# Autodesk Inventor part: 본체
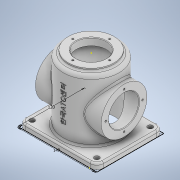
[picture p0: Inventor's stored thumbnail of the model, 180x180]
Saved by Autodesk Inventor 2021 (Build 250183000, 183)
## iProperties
Created: 2021-02
Part Number: 본체
Material: 알루미늄 6061
Document SubType Name: Modeling
Designer: mdu2-97
Density: 2.7 g/cm^3
Appearance: 기본값
Mass: 1251.31 g
Surface Area: 1080.97 cm^2
Volume: 463.448 cm^3
Author: mdu2-97
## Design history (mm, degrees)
sketch "스케치1"
  geometry: L1 (-70, -60)-(70, -60); L2 (70, -60)-(70, 60); L3 (70, 60)-(-70, 60); L4 (-70, 60)-(-70, -60); L5 (-70, -60)-(70, 60); L6 (70, -60)-(-70, 60); 1 further point
  constraints: 12 end point, 2 midpoint, 2 parallel, 1 horizontal, 1 perpendicular
  dimensions: "d0" = 140 distance of L3.end L2.end; "d1" = 120 distance of L2.end L1.end
extrude "돌출1" new body sketch "스케치1" distance "d2" = 10; taper "d3" = 0 deg
sketch "스케치2"
  geometry: 1 further point
sketch "스케치3"
  geometry: C1 r 50 at (0, 0); 1 further point
  constraints: 1 centre point, 1 coincident
  dimensions: "d4" = 100 diameter of C1
extrude "돌출2" join sketch "스케치3" distance "d5" = 110; taper "d6" = 0 deg
sketch "스케치6"
  geometry: 1 further point
sketch "스케치7"
  geometry: C1 r 27 at (0, 0); 1 further point
  constraints: 1 centre point, 1 coincident
  dimensions: "d12" = 54 diameter of C1
extrude "돌출4" cut sketch "스케치7" distance "d13" = 8; taper "d14" = 0 deg
sketch "스케치8"
  geometry: C1 r 42 at (0, 0); 1 further point
  constraints: 1 centre point, 1 coincident
  dimensions: "d15" = 84 diameter of C1
extrude "돌출5" cut sketch "스케치8" extent not by distance; stored distance "d16" = 0; taper "d17" = 0 deg
sketch "스케치9"
  geometry: C1 r 41 at (0, 0); 1 further point
  constraints: 1 centre point, 1 coincident
  dimensions: "d18" = 82 diameter of C1
extrude "돌출6" join sketch "스케치9" distance "d19" = 5; taper "d20" = 0 deg
sketch "스케치10"
  geometry: C1 r 27 at (0, 0) reference; 1 further point
extrude "돌출7" cut sketch "스케치10" extent not by distance; stored distance "d21" = 5; taper "d22" = 0 deg
fillet "모깎기1" dims "d23" = 6
fillet "모깎기2" dims "d24" = 3
node "작업 평면1"
sketch "스케치11"
  geometry: L1 (10, 60)-(10, -60) reference; L2 (125, -41)-(125, 41) reference; L3 (0, 60)-(0, -60) reference; L4 (10, 50)-(10, -50) reference; L5 (114, -50)-(114, 50) reference; L6 (114, 0)-(10, 0); C1 r 41 at (60, 0); 1 further point
  constraints: 2 end point, 2 midpoint, 1 centre point, 1 point on line
  dimensions: "d26" = 82 diameter of C1; "d27" = 60 distance from line of C1.centre L3
extrude "돌출8" join sketch "스케치11" stored distance "d28" = 5; taper "d29" = 0 deg
sketch "스케치12"
  geometry: C1 r 27 at (0, 0); C2 r 41 at (0, 0) reference; 1 further point
  constraints: 1 centre point, 1 coincident
  dimensions: "d30" = 54 diameter of C1
extrude "돌출9" cut sketch "스케치12" stored distance "d31" = 5; taper "d32" = 0 deg
fillet "모깎기3" dims "d33" = 3
sketch "스케치13"
  geometry: 1 further point
fillet "모깎기4" dims "d34" = 12
sketch "스케치14"
  geometry: C1 r 4.5 at (-58, -48); A1 r 12 centre (-58, -48) between (-70, -48) and (-58, -60) reference; A2 r 12 centre (-58, 48) between (-58, 60) and (-70, 48) reference; A3 r 12 centre (58, 48) between (70, 48) and (58, 60) reference; A4 r 12 centre (58, -48) between (58, -60) and (70, -48) reference; 1 further point
  constraints: 1 centre point, 1 coincident
  dimensions: "d35" = 9 diameter of C1
extrude "돌출10" cut sketch "스케치14" extent not by distance; stored distance "d36" = 0; taper "d37" = 0 deg
sketch "스케치15" dims "d38" = 66
  geometry: 3 further points
  constraints: 1 vertical alignment, 2 other
hole "구멍1" sketch "스케치15" at (0, 33) diameter "d39" = 3.242; stored, may be unused: countersink angle "d43" = 90 deg, drill point angle "d45" = 118 deg; dims "d40" = 8, "d41" = 12, "d42" = 2, "d44" = 10
sketch "스케치16" dims "d49" = 66
  geometry: 3 further points
  constraints: 1 coincident, 1 vertical alignment, 2 other
hole "구멍2" sketch "스케치16" at (0, 33) diameter "d50" = 3.242; stored, may be unused: countersink angle "d54" = 90 deg, drill point angle "d56" = 118 deg; dims "d51" = 8, "d52" = 12, "d53" = 2, "d55" = 10
fillet "모깎기5" dims "d60" = 3
chamfer "모따기1" distance "d61" = 1; stored, may be unused: second distance "d62" = 2, angle "d63" = 45 deg
sketch "스케치17"
  geometry: 1 further point
fillet "모깎기6" dims "d64" = 3
fillet "모깎기7" dims "d65" = 3
node "작업 평면3"
sketch "스케치18"
  geometry: L1 (-58, 0)-(58, 0) reference; L2 (0, 151.2)-(0, -25.2) reference; 2 further points
  constraints: 1 point on line, 1 other
  dimensions: "d67" = 66 distance from line of L1 point (0, 66)
feature "엠보싱1" sketch "스케치18" dims "d68" = 0.5, "d69" = 0
node "솔리드1"
mirror "미러1"
mirror "미러2"
mirror "미러3"
pattern_circular "원형 패턴1" dims angle "d47" = 360 deg
mirror "미러4"
pattern_circular "원형 패턴2" dims angle "d58" = 360 deg
node "투영된 루프1"
node "작업 평면2"
node "투영된 루프2"
feature "A9D066F2-1C7D-4E18-AEED-F7BC21143FA4" dims "d39" = 3.242, "d40" = 8, "d41" = 12, "d42" = 2, "d43" = 90 deg, "d44" = 10, "d45" = 118 deg
other parameters: "d25" = 59
